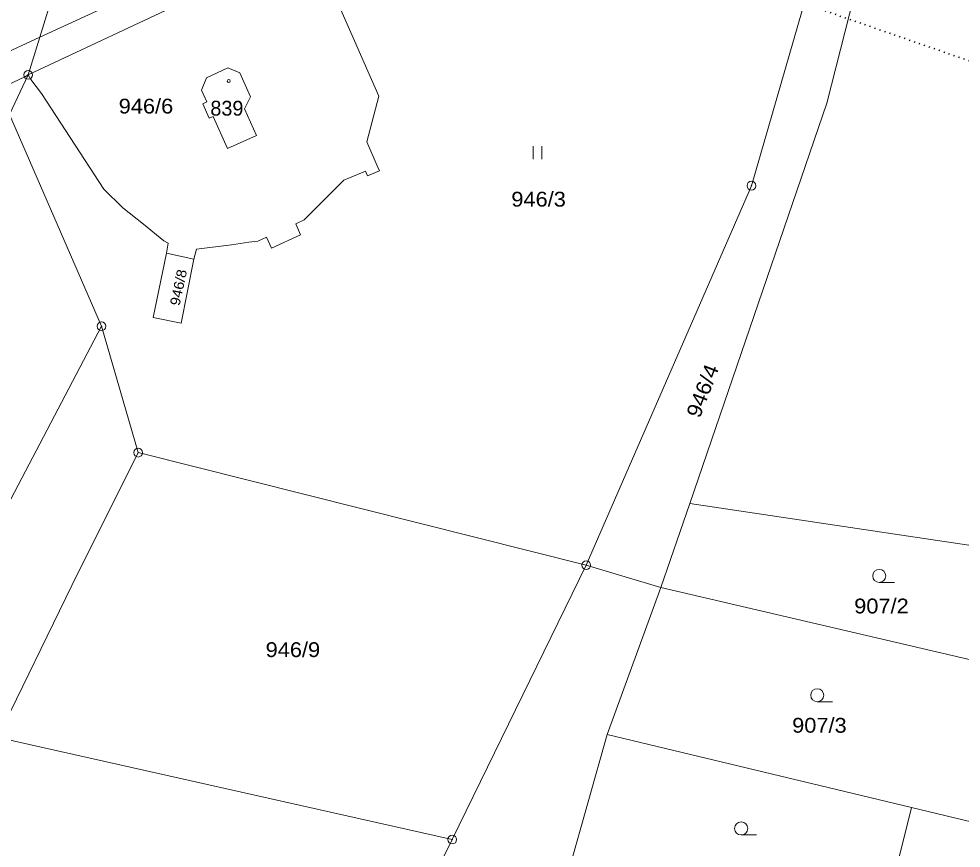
# Model space of a CAD drawing. Extents: x -686207 to -681951, y -1020493 to -1017811.
# Drawn here: x -682620.9 to -682512.8, y -1019020.1 to -1018924.9 of the extents above; entities that cross this region are included whole.
import ezdxf

# ---------------------------------------------------------------- set-up
doc = ezdxf.new("R2010")
doc.units = 0
doc.header["$LTSCALE"] = 0.4
doc.linetypes.add('DOTTED', pattern=[1.5, 0.3, -1.2])
for name, color, linetype, lineweight in [('1', 7, 'Continuous', 13), ('3', 7, 'Continuous', 13), ('4', 7, 'Continuous', 13), ('46', 7, 'DOTTED', 35), ('5', 7, 'Continuous', 13), ('8', 7, 'Continuous', 13)]:
    doc.layers.add(name, color=color, linetype=linetype, lineweight=lineweight)
doc.layers.add('2', color=7, linetype='Continuous')

msp = doc.modelspace()

# ---------------------------------------------------------------- linework, layer by layer
at = {"layer": '1'}
for p, q in [((-682595.35, -1018919.84), (-682619.86, -1018931.35)), ((-682604, -1018951.82), (-682600.85, -1018952.49)), ((-682611.44, -1018960.2), (-682607.23, -1018974.7)), ((-682607.23, -1018974.7), (-682614.83, -1018989.95)), ((-682607.23, -1018974.7), (-682555.81, -1018987.61)), ((-682543.91, -1018980.54), (-682547.25, -1018990.17)), ((-682543.91, -1018980.54), (-682497.6, -1018987.44)), ((-682571.19, -1019019.11), (-682555.81, -1018987.61)), ((-682614.83, -1018989.95), (-682623.36, -1019007.38)), ((-682547.25, -1018990.17), (-682505.29, -1018999.99)), ((-682553.42, -1019007.06), (-682557.77, -1019022.5)), ((-682623.36, -1019007.38), (-682571.19, -1019019.11)), ((-682510.51, -1019017.34), (-682518.49, -1019015.41)), ((-682571.19, -1019019.11), (-682611.68, -1019099.92))]:
    msp.add_line(p, q, dxfattribs=at)
for points in [[(-682555.81, -1018987.61), (-682536.86, -1018944.06), (-682522.31, -1018893.72), (-682521.99, -1018888.66)], [(-682519.84, -1018901.64), (-682528.19, -1018934.6), (-682543.91, -1018980.54)], [(-682615.08, -1018915.78), (-682615.96, -1018918.65), (-682618.53, -1018927.03), (-682619.86, -1018931.35)], [(-682588.89, -1018916.8), (-682588.93, -1018916.92), (-682588.86, -1018919.91), (-682584.53, -1018922.62), (-682579.63, -1018933.79), (-682580.98, -1018939.01), (-682579.79, -1018941.78), (-682579.54, -1018942.36), (-682580.92, -1018942.95), (-682581.16, -1018942.38), (-682583.62, -1018943.43), (-682588.18, -1018947.98), (-682589.16, -1018948.44), (-682588.59, -1018949.7), (-682591.93, -1018951.22), (-682592.5, -1018949.96), (-682593.51, -1018950.42), (-682594.53, -1018950.54)], [(-682619.86, -1018931.35), (-682620.16, -1018931.52), (-682634.27, -1018938.17), (-682645.59, -1018943.34)], [(-682619.86, -1018931.35), (-682622, -1018935.9), (-682611.44, -1018960.2)], [(-682606.64, -1018948.48), (-682609.01, -1018946.6), (-682611.17, -1018944.46), (-682618.33, -1018933.47), (-682619.57, -1018931.88), (-682619.86, -1018931.35)], [(-682604, -1018951.82), (-682603.78, -1018950.67), (-682604.28, -1018950.38), (-682606.64, -1018948.48)], [(-682594.53, -1018950.54), (-682596.52, -1018950.86), (-682600.56, -1018951.33), (-682600.85, -1018952.49)], [(-682600.85, -1018952.49), (-682602.31, -1018959.84), (-682605.51, -1018959.18), (-682604, -1018951.82)], [(-682764.49, -1019199.84), (-682747.6, -1019171.27), (-682736.43, -1019153.9), (-682718.43, -1019128.84), (-682680.44, -1019078.6), (-682636.45, -1019008.73), (-682626.86, -1018989.53), (-682611.44, -1018960.2)], [(-682555.81, -1018987.61), (-682547.25, -1018990.17), (-682553.42, -1019007.06), (-682518.49, -1019015.41)], [(-682518.49, -1019015.41), (-682519.88, -1019020.96), (-682522.31, -1019030.65)]]:
    msp.add_lwpolyline(points, dxfattribs=at)
msp.add_lwpolyline([(-682595.57, -1018931.1), (-682596.95, -1018930.54), (-682599.41, -1018931.67), (-682599.97, -1018933.1), (-682599.37, -1018934.45), (-682599.82, -1018934.65), (-682599.08, -1018936.33), (-682598.62, -1018936.12), (-682596.98, -1018939.8), (-682593.67, -1018938.32), (-682595.05, -1018935.23), (-682594.36, -1018933.85)], close=True, dxfattribs=at)
at = {"layer": '3'}
for p, q in [((-682561.921, -1018941.02), (-682561.921, -1018939.52)), ((-682560.92, -1018941.02), (-682560.92, -1018939.52)), ((-682522.183, -1018989.6), (-682520.433, -1018989.6)), ((-682529.303, -1019003.29), (-682527.553, -1019003.29)), ((-682538.033, -1019018.58), (-682536.283, -1019018.58))]:
    msp.add_line(p, q, dxfattribs=at)
for centre in [(-682522.1829, -1018988.8498), (-682529.3029, -1019002.5398), (-682538.0329, -1019017.8298)]:
    msp.add_circle(centre, 0.75, dxfattribs=at)
at = {"layer": '4'}
for p, q in [((-682618.53, -1018927.03), (-682594.03, -1018915.71)), ((-682635.54, -1018934.88), (-682618.53, -1018927.03))]:
    msp.add_line(p, q, dxfattribs=at)
at = {"layer": '46'}
msp.add_lwpolyline([(-682492.516, -1018981.168), (-682494.839, -1018935.641), (-682547.461, -1018917.387)], dxfattribs=at)
at = {"layer": '5'}
msp.add_circle((-682596.8368, -1018932.0492), 0.175, dxfattribs=at)
at = {"layer": '8'}
for centre, radius in [((-682619.86, -1018931.3499), 0.5), ((-682619.86, -1018931.3499), 0.0303), ((-682536.86, -1018944.0599), 0.5), ((-682536.86, -1018944.0599), 0.0303), ((-682611.44, -1018960.1999), 0.5), ((-682611.44, -1018960.1999), 0.0303), ((-682607.23, -1018974.6999), 0.5), ((-682607.23, -1018974.6999), 0.0303), ((-682555.81, -1018987.6099), 0.5), ((-682555.81, -1018987.6099), 0.0303), ((-682571.19, -1019019.1099), 0.5), ((-682571.19, -1019019.1099), 0.0303)]:
    msp.add_circle(centre, radius, dxfattribs=at)

# ---------------------------------------------------------------- texts
at = {"layer": '2', "width": 1.1}
for s, p in [('946/6', (-682609.47, -1018935.78)), ('946/3', (-682564.41, -1018946.46)), ('907/2', (-682525.063, -1018993.15)), ('946/9', (-682592.61, -1018998.16)), ('907/3', (-682532.183, -1019006.84))]:
    msp.add_text(s, height=1.7, dxfattribs=at).set_placement(p)
at = {"layer": '2'}
msp.add_text('839', height=1.7, dxfattribs=at).set_placement((-682598.95, -1018936.02))
at = {"layer": '2', "width": 1.1}
for s, height, rotation, p in [('946/8', 1.139, 78, (-682602.489, -1018957.905)), ('946/4', 1.7, 69, (-682542.786, -1018970.834))]:
    msp.add_text(s, height=height, rotation=rotation, dxfattribs=at).set_placement(p)

doc.saveas('drawing.dxf')
